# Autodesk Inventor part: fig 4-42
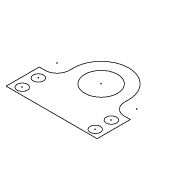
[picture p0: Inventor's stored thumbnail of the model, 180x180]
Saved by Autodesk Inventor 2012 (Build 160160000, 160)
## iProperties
Created: 2004-05
Part Number: fig 4-42
Document SubType Name: Modeling
Designer: CADCIM Technologies
Manufacturer: Standard
Standards Organization: Custom
Density: 1 g/cm^3
Material: Default
Author: CADCIM Technologies
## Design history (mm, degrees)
sketch "Sketch1"
  geometry: L1 (41.331, 50.432)-(41.331, 48.38); L2 (35.331, 42.38)-(32.489, 42.38); L3 (32.489, 42.38)-(32.489, 26.047); L4 (68.481, 50.432)-(68.481, 48.38); L5 (74.481, 42.38)-(77.323, 42.38); L6 (77.323, 42.38)-(77.323, 26.047); L7 (32.489, 26.047)-(77.323, 26.047); C1 r 8.09 at (54.906, 50.432); C2 r 2.534 at (36.931, 29.558); C3 r 2.534 at (36.931, 37.474); C4 r 2.534 at (72.881, 37.474); C5 r 2.534 at (72.881, 29.558); A1 r 13.575 centre (54.906, 50.432) between (68.481, 50.432) and (41.331, 50.432); A2 r 6 centre (35.331, 48.38) between (35.331, 42.38) and (41.331, 48.38); A3 r 6 centre (74.481, 48.38) between (68.481, 48.38) and (74.481, 42.38)
  constraints: 14 end point, 8 centre point, 6 point on circle, 6 tangent, 3 equal length, 2 horizontal, 2 perpendicular, 1 coincident, 1 equal radius, 1 parallel, 1 vertical
